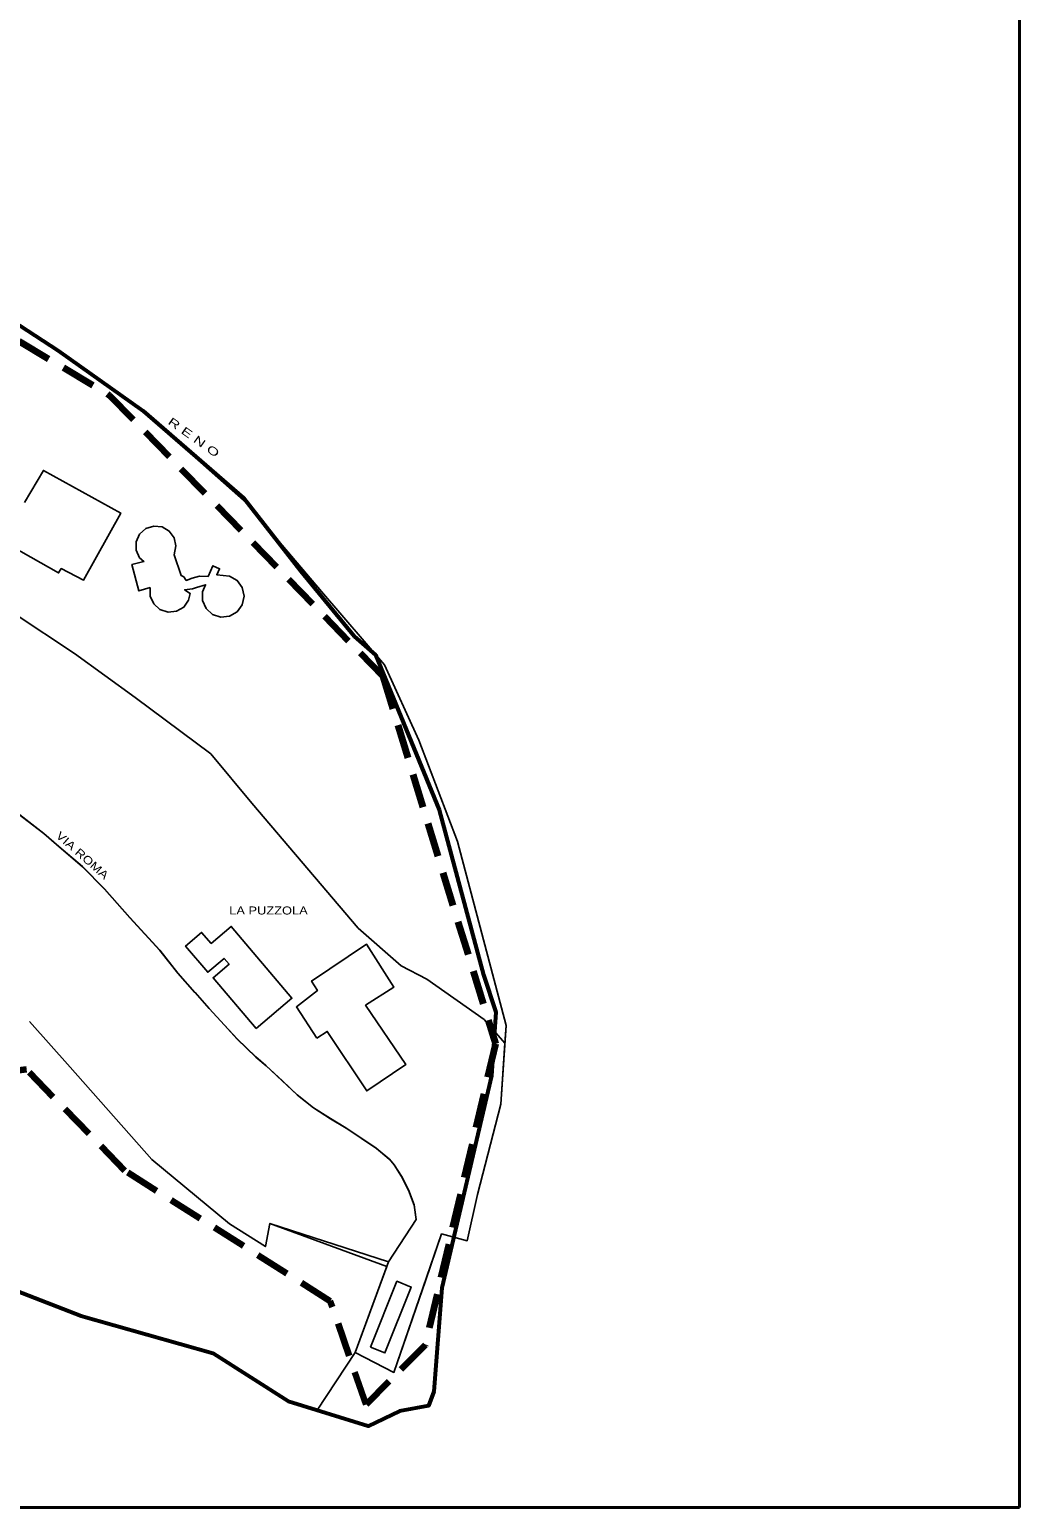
# Model space of a CAD drawing. Extents: x 654952 to 658955, y 890426 to 894481.
# Drawn here: x 658609 to 658955, y 890426 to 890943 of the extents above; entities that cross this region are included whole.
import ezdxf

# ---------------------------------------------------------------- set-up
doc = ezdxf.new("R2010")
doc.units = 0
doc.header["$LTSCALE"] = 4
doc.linetypes.add('MEDIUM_DASHED', pattern=[4.5, 3, -1.5])
for name, color, linetype, lineweight in [('1', 7, 'Continuous', 25), ('35', 7, 'Continuous', 25), ('4', 7, 'Continuous', 25), ('55', 7, 'Continuous', 25), ('59', 7, 'Continuous', 53), ('60', 7, 'Continuous', 35), ('7', 7, 'MEDIUM_DASHED', 100)]:
    doc.layers.add(name, color=color, linetype=linetype, lineweight=lineweight)
doc.layers.add('58', color=7, linetype='Continuous')

msp = doc.modelspace()

# ---------------------------------------------------------------- linework, layer by layer
at = {"layer": '1'}
for points in [[(658734.45, 890511.82), (658722.78, 890480.06), (658736.33, 890473.12), (658752.96, 890521.61), (658761.95, 890519.26), (658765.57, 890535.45), (658773.72, 890567.09), (658775.59, 890594.61), (658758.58, 890658.97), (658744.97, 890694.47), (658733.05, 890720.87), (658710.93, 890746.45), (658684.67, 890777.43), (658645.53, 890812.09), (658603.84, 890840.99), (658568.96, 890862.45), (658494.56, 890903.83), (658472.38, 890915.2), (658438.87, 890927.61), (658423.05, 890929.48)], [(658600.07, 890740.44), (658603.34, 890738.83), (658624.52, 890724.75), (658645.68, 890709.35), (658672.24, 890689.64), (658686.53, 890672.4), (658723.74, 890628.69), (658738.84, 890615.48), (658747.88, 890610.82), (658767.93, 890596.66), (658775.17, 890588.4), (658775.59, 890594.61), (658758.58, 890658.97), (658744.97, 890694.47), (658733.05, 890720.87), (658710.93, 890746.45), (658684.67, 890777.43), (658645.53, 890812.09), (658603.84, 890840.99), (658568.96, 890862.45), (658494.56, 890903.83), (658472.38, 890915.2), (658443.99, 890925.71)], [(658603.34, 890738.83), (658624.52, 890724.75), (658645.68, 890709.35), (658672.24, 890689.64), (658686.53, 890672.4), (658723.74, 890628.69), (658738.84, 890615.48), (658747.88, 890610.82), (658767.93, 890596.66), (658775.17, 890588.4), (658775.59, 890594.61), (658758.58, 890658.97), (658744.97, 890694.47), (658733.05, 890720.87), (658710.93, 890746.45), (658684.67, 890777.43), (658645.53, 890812.09), (658603.84, 890840.99)], [(658604.34, 890669.07), (658613.77, 890661.75), (658619.07, 890657.16), (658627.32, 890650.15), (658634.98, 890642.35), (658643.9, 890632.31), (658654.4, 890620.8), (658660.64, 890612.85), (658666.68, 890606.08), (658671.66, 890600.52), (658677.03, 890594.68), (658681.45, 890589.83), (658688.01, 890583.54), (658691.53, 890580.48), (658697.26, 890575.17), (658702.53, 890570.15), (658708.16, 890565.7), (658714.11, 890561.87), (658719.56, 890558.61), (658724.78, 890555.18), (658730.18, 890551.49), (658734.72, 890547.74), (658736.43, 890545.76), (658738.98, 890541.75), (658741.46, 890536.99), (658743.4, 890531.67), (658744.1, 890526.67), (658734.45, 890511.82)]]:
    msp.add_lwpolyline(points, dxfattribs=at)
at = {"layer": '35'}
for points in [[(658733.81, 890510.2), (658734.42, 890511.87), (658744.1, 890526.67), (658743.36, 890531.77), (658741.42, 890537.09), (658738.94, 890541.85), (658736.39, 890545.86), (658734.68, 890547.84), (658730.14, 890551.59), (658724.74, 890555.28), (658719.52, 890558.71), (658714.07, 890561.97), (658708.12, 890565.8), (658702.49, 890570.25), (658697.23, 890575.22), (658691.5, 890580.53), (658687.98, 890583.59), (658681.42, 890589.88), (658677, 890594.73), (658671.63, 890600.57), (658666.64, 890606.18), (658660.6, 890612.95), (658654.36, 890620.9), (658643.86, 890632.41), (658634.94, 890642.45), (658627.29, 890650.2), (658619.03, 890657.26), (658613.74, 890661.8), (658604.31, 890669.12)], [(658608.75, 890595.92), (658623.02, 890579.96), (658651.55, 890547.7), (658678.7, 890525.17), (658691.29, 890517.21), (658692.88, 890525.32), (658733.81, 890510.2)], [(658692.88, 890525.32), (658691.29, 890517.21), (658678.7, 890525.17), (658651.55, 890547.7), (658623.02, 890579.96), (658608.75, 890595.92)], [(658439.45, 890554.58), (658487.84, 890539.37), (658528.8, 890529.12), (658583.71, 890509.56), (658626.83, 890492.8), (658673.05, 890479.76), (658699.42, 890463), (658709.42, 890459.89)], [(658709.42, 890459.89), (658722.75, 890480.11), (658733.81, 890510.2), (658692.88, 890525.32)]]:
    msp.add_lwpolyline(points, dxfattribs=at)
at = {"layer": '4'}
msp.add_lwpolyline([(658606.97, 890777.62), (658613.61, 890788.88), (658640.7, 890773.92), (658627.61, 890750.42), (658619.84, 890754.54), (658618.89, 890753.02), (658558.02, 890787.4)], dxfattribs=at)
for points in [[(658651.02, 890747.88), (658646.96, 890746.72), (658644.6, 890755.9), (658648.77, 890756.96), (658647.29, 890758.3), (658646.11, 890760.96), (658646.11, 890763.88), (658647.29, 890766.54), (658649.46, 890768.5), (658652.24, 890769.4), (658655.14, 890769.08), (658657.66, 890767.62), (658659.38, 890765.26), (658659.99, 890762.42), (658659.34, 890759.38), (658661.8, 890752.08), (658662.71, 890751.58), (658663.59, 890750.38), (658665.64, 890751.1), (658668.24, 890751.9), (658671.27, 890751.72), (658672.95, 890755.52), (658675.29, 890754.44), (658674.3, 890752.34), (658678.78, 890751.86), (658681.43, 890750.34), (658683.23, 890747.86), (658683.87, 890744.86), (658683.23, 890741.86), (658681.43, 890739.38), (658678.78, 890737.84), (658675.73, 890737.52), (658672.81, 890738.48), (658670.54, 890740.52), (658669.29, 890743.32), (658669.29, 890746.38), (658670.36, 890748.88), (658667.18, 890747.9), (658665.83, 890747.4), (658663.03, 890747.1), (658664.96, 890745.84), (658664.44, 890743.42), (658662.71, 890741.04), (658660.15, 890739.56), (658657.22, 890739.26), (658654.41, 890740.16), (658652.22, 890742.14), (658651.02, 890744.84)], [(658688.03, 890593.54), (658672.99, 890611.3), (658678.58, 890616.04), (658676.85, 890618.04), (658671.13, 890613.2), (658663.35, 890622.4), (658668.99, 890627.16), (658672.33, 890623.3), (658679.36, 890629.24), (658700.57, 890604.14)], [(658709.3, 890590.2), (658702.18, 890601.08), (658709.54, 890606.8), (658707.49, 890610.1), (658726.65, 890623.08), (658736.33, 890608.04), (658726.36, 890601.64), (658740.45, 890580.92), (658726.82, 890571.68), (658712.98, 890592.5)], [(658728.12, 890481.96), (658733.15, 890479.96), (658742.37, 890503.04), (658737.35, 890505.06)]]:
    msp.add_lwpolyline(points, close=True, dxfattribs=at)
at = {"layer": '55'}
for points in [[(658775.17, 890588.4), (658767.93, 890596.66), (658747.88, 890610.82), (658738.84, 890615.48), (658723.74, 890628.69), (658686.53, 890672.4), (658672.24, 890689.64), (658645.68, 890709.35), (658624.52, 890724.75), (658603.34, 890738.83), (658600.07, 890740.44)], [(658608.75, 890595.92), (658623.02, 890579.96), (658651.55, 890547.7), (658678.7, 890525.17), (658691.29, 890517.21), (658692.88, 890525.32)], [(658747.33, 890505.2), (658752.96, 890521.61), (658761.95, 890519.26), (658765.57, 890535.45), (658773.72, 890567.09), (658775.17, 890588.4)], [(658692.88, 890525.32), (658734.45, 890511.82), (658722.78, 890480.06), (658736.33, 890473.12), (658747.33, 890505.2)]]:
    msp.add_lwpolyline(points, dxfattribs=at)
at = {"layer": '59'}
msp.add_lwpolyline([(658583.4, 890853.83), (658618.77, 890830.85), (658648.55, 890809.74), (658683.6, 890779.32), (658703.77, 890753.55), (658722.38, 890730.89), (658729.83, 890724.37), (658752.16, 890670.05), (658767.67, 890612.31), (658772.01, 890599.27), (658770.46, 890576.92), (658753.09, 890502.73), (658750.3, 890466.41), (658748.43, 890461.45), (658738.2, 890459.58), (658727.34, 890454.31), (658699.42, 890463), (658673.05, 890479.76), (658626.83, 890492.8), (658583.71, 890509.56)], dxfattribs=at)
at = {"layer": '60', "lineweight": 40}
msp.add_lwpolyline([(657055.17, 894480.74), (658955.28, 894480.74), (658955.28, 890425.88), (657055.17, 890425.88)], close=True, dxfattribs=at)
at = {"layer": '7'}
msp.add_lwpolyline([(658330.3, 891246.22), (658327.72, 891183.18), (658338.55, 891136.81), (658353.44, 891095.71), (658449.21, 890955.48), (658420.28, 890931.68), (658481.44, 890907.81), (658636.65, 890815.27), (658732.37, 890716.91), (658771.82, 890588.13), (658747.24, 890482.65), (658726.56, 890461.94), (658714.04, 890498.12), (658642.13, 890543.72), (658607.69, 890579.19), (658520.59, 890568.04), (658475.02, 890599.46), (658360.56, 890605.54), (658254.22, 890706.88), (658248.14, 890844.7), (658184.33, 890889.29), (658123.56, 891003.8)], dxfattribs=at)

# ---------------------------------------------------------------- texts
at = {"layer": '58'}
for s, height, rotation, width, p in [('R E N O', 2.798, 324.49, 1.5, (658656.93, 890805.38)), ('VIA ROMA', 2.801, 318.619, 1.25, (658617.74, 890660.66))]:
    msp.add_text(s, height=height, rotation=rotation, dxfattribs=dict(at, width=width)).set_placement(p)
at = {"layer": '58', "width": 1.2}
msp.add_text('LA PUZZOLA', height=2.801, dxfattribs=at).set_placement((658678.65, 890633.43))

doc.saveas('drawing.dxf')
